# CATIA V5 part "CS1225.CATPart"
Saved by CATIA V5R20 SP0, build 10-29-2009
Part number: CS1225
Revision: 4
Definition: design
Nomenclature: CS1225
Source: made
Description: NOT SPECIFIED
Bounding box of the stored display mesh (mm): x -23.825 to 24, y -24 to 24, z -45 to 12
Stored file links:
  C:\Users\Raffaele\Desktop\3D X SITO CF\BOLEX\20-TILTED COLUMN SUPPORT\CS1225.CATPart
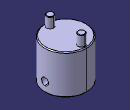
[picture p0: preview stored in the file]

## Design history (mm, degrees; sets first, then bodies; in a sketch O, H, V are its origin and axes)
Body1 "MANIFOLD_SOLID_BREP #711" (main body)
  Solid1: solid without history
